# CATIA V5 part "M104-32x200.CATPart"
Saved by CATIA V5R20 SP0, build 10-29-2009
Part number: M104-32x200
Source: Unknown
Bounding box of the stored display mesh (mm): x -15.868 to 15.868, y -15.868 to 15.868, z 0 to 200
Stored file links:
  C:\Users\Utente\Desktop\IO LAVORO\3D X SITO CF\X SITO\M104\M104-32x200.CATPart

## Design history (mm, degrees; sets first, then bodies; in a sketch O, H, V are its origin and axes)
Body1 (main body)
  Solid1 "PartBody": solid without history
